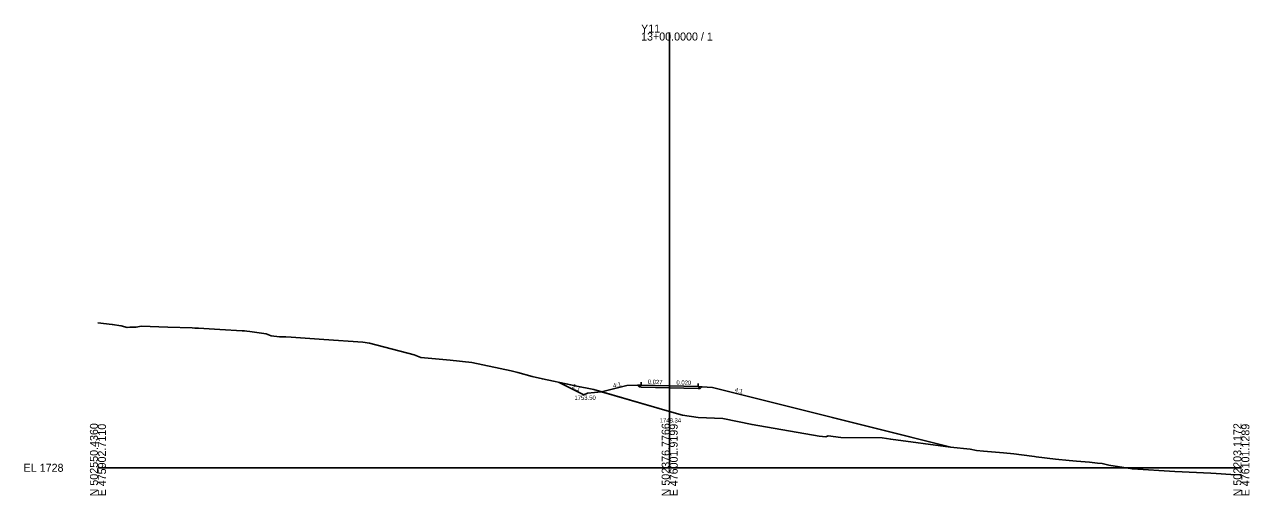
# Model space of a CAD drawing. Extents: x -76 to 353, y -10 to 8186.
# Drawn here: x -75.7 to 352.8, y 5990.3 to 6155.1 of the extents above; entities that cross this region are included whole.
import ezdxf

# ---------------------------------------------------------------- set-up
doc = ezdxf.new("R2010")
doc.units = 0
for name, color, linetype in [('Exist Cross Section Cell', 7, 'Continuous'), ('Exist XS Center Line Elevation Label', 7, 'Continuous'), ('Exist XS Ground Line', 7, 'Continuous'), ('Prop XS DDE', 7, 'Continuous'), ('Prop XS DDE Earthwork Shape', 7, 'Continuous'), ('Prop XS Ditch Slope Text', 7, 'Continuous'), ('Prop XS Ditch Standard Text', 7, 'Continuous'), ('Prop XS Dump Level', 7, 'Continuous'), ('Prop XS Earthwork Shape', 7, 'Continuous'), ('Prop XS EOT Tick Mark', 7, 'Continuous'), ('Prop XS Finish Grade', 7, 'Continuous'), ('Prop XS Finish Grade Earthwork', 7, 'Continuous'), ('Prop XS Finish Grade Pavement', 7, 'Continuous'), ('Prop XS Hydro Fill Slope Data', 7, 'Continuous'), ('Prop XS Hydro Typical Ditch Data', 7, 'Continuous'), ('Prop XS Pvmt Edge Slope', 7, 'Continuous'), ('Prop XS SE Text', 7, 'Continuous'), ('Prop XS Shoulder Borrow Shape', 7, 'Continuous'), ('Prop XS Side Slope Text', 7, 'Continuous'), ('Prop XS Subgrade Earthwork', 7, 'Continuous'), ('Scratch_Level_3', 7, 'Continuous'), ('Scratch_Level_6', 7, 'Continuous')]:
    doc.layers.add(name, color=color, linetype=linetype)

msp = doc.modelspace()

# ---------------------------------------------------------------- linework, layer by layer
at = {"layer": 'Exist Cross Section Cell'}
for p, q in [((150, 6000), (150, 6152.25)), ((-50, 6000), (150, 6000)), ((150, 6000), (350, 6000))]:
    msp.add_line(p, q, dxfattribs=at)
at = {"layer": 'Exist XS Ground Line'}
msp.add_lwpolyline([(-50, 6050.75), (-45.01, 6050.13), (-41.93, 6049.61), (-39.76, 6049.05), (-38.89, 6049.14), (-36.61, 6049.22), (-34.83, 6049.49), (-25.55, 6049.18), (-17.02, 6048.92), (-16.05, 6048.87), (-14.85, 6048.83), (-7.39, 6048.38), (0.45, 6047.9), (1.31, 6047.85), (2.14, 6047.79), (3.16, 6047.66), (8.85, 6046.82), (10.57, 6046.19), (13.53, 6045.8), (15.71, 6045.78), (17.62, 6045.71), (29.07, 6044.9), (42.63, 6043.91), (45.05, 6043.64), (60.59, 6039.48), (62.95, 6038.54), (73.18, 6037.59), (80.74, 6036.83), (94.58, 6033.89), (96.92, 6033.36), (101.94, 6031.92), (105.47, 6031.07), (115.37, 6028.96), (116.4, 6028.76), (116.99, 6028.62), (123.42, 6027.35), (150, 6019.69), (154.44, 6018.41), (159.95, 6017.64), (168.56, 6017.23), (178.85, 6015.12), (202.32, 6011.11), (204.66, 6010.88), (205.49, 6011.16), (209.93, 6010.65), (224.32, 6010.49), (227.36, 6009.96), (248.21, 6007.22), (255.14, 6006.48), (257.39, 6006.04), (259.82, 6005.85), (266.74, 6005.23), (270.35, 6004.85), (276.68, 6004.04), (277.68, 6003.91), (278.25, 6003.83), (285.01, 6003.02), (289.77, 6002.53), (292.34, 6002.27), (296.84, 6001.93), (299.68, 6001.66), (301.29, 6001.49), (303.61, 6000.97), (311.91, 5999.58), (326.71, 5998.71), (339.37, 5998.13), (341.18, 5997.95), (346.27, 5997.63), (350, 5997.56)], dxfattribs=at)
at = {"layer": 'Prop XS DDE'}
for p, q in [((119.95, 6025.5), (111.29, 6029.83)), ((121.21, 6026.13), (119.95, 6025.5)), ((126.21, 6026.55), (121.21, 6026.13))]:
    msp.add_line(p, q, dxfattribs=at)
at = {"layer": 'Prop XS DDE Earthwork Shape'}
for points in [[(116.99, 6028.62), (123.42, 6027.35), (126.21, 6026.55), (121.21, 6026.13), (119.95, 6025.5), (111.29, 6029.83), (115.37, 6028.96), (116.4, 6028.76)], [(116.4, 6028.76), (116.99, 6028.62), (123.42, 6027.35), (126.21, 6026.55), (121.21, 6026.13), (119.95, 6025.5), (111.29, 6029.83), (115.37, 6028.96)]]:
    msp.add_lwpolyline(points, close=True, dxfattribs=at)
at = {"layer": 'Prop XS Dump Level'}
for p, q in [((140, 6028.91), (150, 6028.65)), ((150, 6028.65), (160, 6028.45))]:
    msp.add_line(p, q, dxfattribs=at)
at = {"layer": 'Prop XS Earthwork Shape'}
msp.add_lwpolyline([(224.32, 6010.49), (227.36, 6009.96), (248.21, 6007.22), (248.36, 6007.21), (165, 6028.05), (161.26, 6028.35), (160.68, 6027.77), (160, 6027.78), (150, 6027.98), (140, 6028.25), (139.35, 6028.26), (138.74, 6028.87), (135, 6028.75), (126.21, 6026.55), (150, 6019.69), (154.44, 6018.41), (159.95, 6017.64), (168.56, 6017.23), (178.85, 6015.12), (202.32, 6011.11), (204.66, 6010.88), (205.49, 6011.16), (209.93, 6010.65)], close=True, dxfattribs=at)
at = {"layer": 'Prop XS EOT Tick Mark'}
for p, q in [((140, 6028.91), (140, 6029.91)), ((160, 6028.45), (160, 6029.45))]:
    msp.add_line(p, q, dxfattribs=at)
at = {"layer": 'Prop XS Finish Grade'}
for p, q in [((140, 6028.91), (138.74, 6028.87)), ((160, 6028.45), (161.26, 6028.35))]:
    msp.add_line(p, q, dxfattribs=at)
at = {"layer": 'Prop XS Finish Grade Earthwork'}
for p, q in [((135, 6028.75), (126.21, 6026.55)), ((138.74, 6028.87), (135, 6028.75)), ((161.26, 6028.35), (165, 6028.05)), ((165, 6028.05), (248.36, 6007.21))]:
    msp.add_line(p, q, dxfattribs=at)
at = {"layer": 'Prop XS Finish Grade Pavement'}
for p, q in [((140, 6028.91), (150, 6028.65)), ((150, 6028.65), (160, 6028.45))]:
    msp.add_line(p, q, dxfattribs=at)
at = {"layer": 'Prop XS Hydro Fill Slope Data'}
msp.add_line((165, 6028.05), (248.39, 6007.2), dxfattribs=at)
at = {"layer": 'Prop XS Hydro Typical Ditch Data'}
msp.add_line((135, 6028.75), (126.21, 6026.55), dxfattribs=at)
at = {"layer": 'Prop XS Pvmt Edge Slope'}
for p, q in [((140, 6028.91), (139.35, 6028.26)), ((160, 6028.45), (160.68, 6027.77))]:
    msp.add_line(p, q, dxfattribs=at)
at = {"layer": 'Prop XS Shoulder Borrow Shape'}
for points in [[(139.35, 6028.26), (138.74, 6028.87), (140, 6028.91)], [(139.35, 6028.26), (138.74, 6028.87), (140, 6028.91)], [(160, 6028.45), (160.68, 6027.77), (161.26, 6028.35)], [(160, 6028.45), (160.68, 6027.77), (161.26, 6028.35)]]:
    msp.add_lwpolyline(points, close=True, dxfattribs=at)
at = {"layer": 'Prop XS Subgrade Earthwork'}
for p, q in [((139.35, 6028.26), (138.74, 6028.87)), ((140, 6028.25), (139.35, 6028.26)), ((150, 6027.98), (140, 6028.25)), ((160, 6027.78), (150, 6027.98)), ((160, 6027.78), (160.68, 6027.77)), ((160.68, 6027.77), (161.26, 6028.35))]:
    msp.add_line(p, q, dxfattribs=at)
at = {"layer": 'Scratch_Level_3'}
for p, q in [((111.29, 6029.83), (119.95, 6025.5)), ((119.95, 6025.5), (121.21, 6026.13)), ((121.21, 6026.13), (126.21, 6026.55)), ((126.21, 6026.55), (123.42, 6027.35))]:
    msp.add_line(p, q, dxfattribs=at)
msp.add_lwpolyline([(123.42, 6027.35), (116.99, 6028.62), (116.4, 6028.76), (115.37, 6028.96), (111.29, 6029.83)], dxfattribs=at)
at = {"layer": 'Scratch_Level_6'}
msp.add_line((165, 6028.05), (234.53, 6010.66), dxfattribs=at)

# ---------------------------------------------------------------- texts
at = {"layer": 'Exist Cross Section Cell'}
for s, p in [('Y11', (140, 6152.25)), ('13+00.0000 / 1', (140, 6149.45)), ('EL 1728', (-76, 5998.6))]:
    msp.add_text(s, height=2.8, dxfattribs=at).set_placement(p)
for s, p in [('N 502550.4360', (-50, 5990)), ('E 475902.7110', (-47.2, 5990)), ('N 502376.7766', (150, 5990)), ('E 476001.9199', (152.8, 5990)), ('N 502203.1172', (350, 5990)), ('E 476101.1289', (352.8, 5990))]:
    msp.add_text(s, height=2.8, rotation=90, dxfattribs=at).set_placement(p)
at = {"layer": 'Exist XS Center Line Elevation Label'}
msp.add_text('1748.34', height=1.5, dxfattribs=at).set_placement((146.52, 6015.84))
at = {"layer": 'Prop XS Ditch Slope Text'}
msp.add_text('4:1', height=1.5, rotation=14.0362, dxfattribs=at).set_placement((130.38, 6027.96))
at = {"layer": 'Prop XS Ditch Standard Text'}
msp.add_text('1753.50', height=1.5, dxfattribs=at).set_placement((116.67, 6023.75))
at = {"layer": 'Prop XS Dump Level'}
for p in [(135, 6028.71), (165, 6028.01)]:
    msp.add_text('Case1', height=0.04, dxfattribs=at).set_placement(p)
at = {"layer": 'Prop XS SE Text'}
for s, rotation, p in [('0.027', 358.4786, (142.33, 6029.35)), ('0.020', 358.8542, (152.35, 6029.1))]:
    msp.add_text(s, height=1.5, rotation=rotation, dxfattribs=at).set_placement(p)
at = {"layer": 'Prop XS Side Slope Text'}
for s, rotation, p in [('2:1', 333.4349, (115.75, 6027.99)), ('4:1', 345.9638, (172.66, 6026.63))]:
    msp.add_text(s, height=1.5, rotation=rotation, dxfattribs=at).set_placement(p)

doc.saveas('drawing.dxf')
